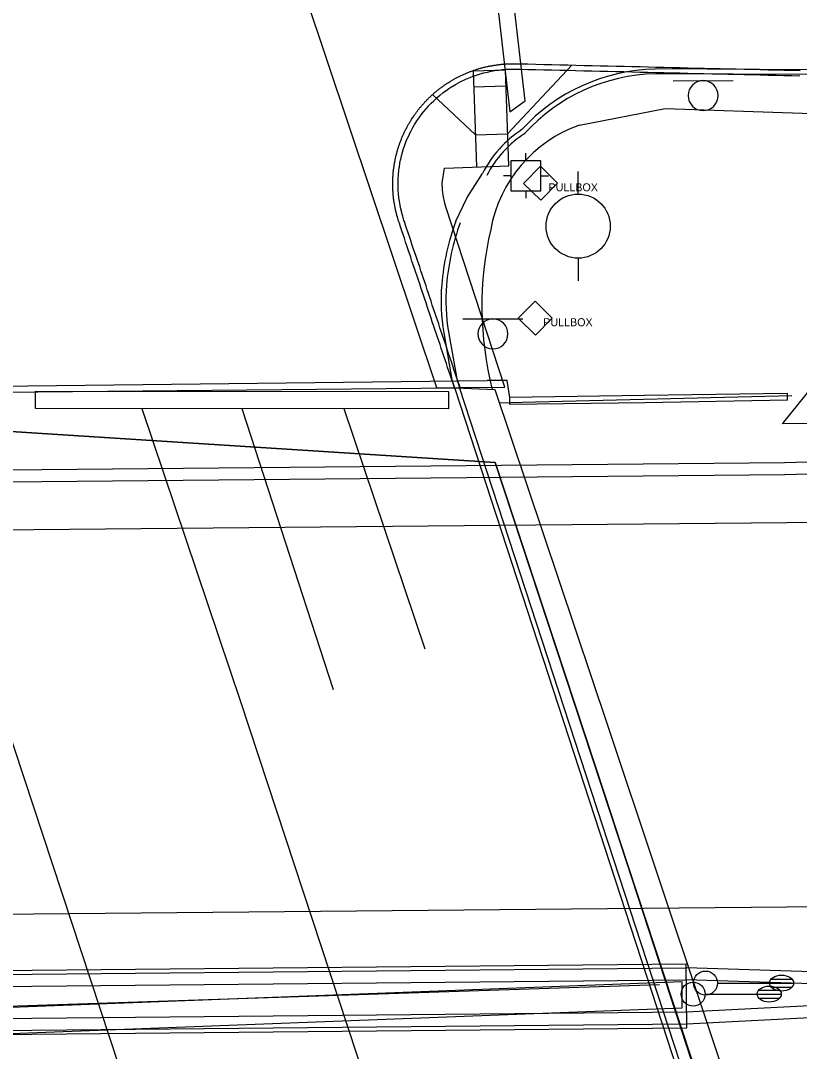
# Model space of a CAD drawing. Extents: x 2145380 to 2157287, y 139568 to 149130.
# Drawn here: x 2147326.9 to 2147424.2, y 143054.1 to 143182.8 of the extents above; entities that cross this region are included whole.
import ezdxf

# ---------------------------------------------------------------- set-up
doc = ezdxf.new("R2010")
doc.units = 0
for name, color, linetype in [('Default', 7, 'Continuous'), ('PR_PREVIOUSLY CONSTRUCTED', 7, 'Continuous'), ('TOPO_Asphalt', 7, 'Continuous'), ('TOPO_Bridge', 7, 'Continuous'), ('TOPO_BRIDGE_Floor Deck', 7, 'Continuous'), ('TOPO_BRIDGE_Low Beam', 7, 'Continuous'), ('TOPO_BRIDGE_Pier', 7, 'Continuous'), ('TOPO_BRIDGE_Pier Cap', 7, 'Continuous'), ('TOPO_Curb Back', 7, 'Continuous'), ('TOPO_Guardrail', 7, 'Continuous'), ('TOPO_Light Pole', 7, 'Continuous'), ('TOPO_Misc Line', 7, 'Continuous'), ('TOPO_Power Pole', 7, 'Continuous'), ('TOPO_Power Pullbox', 7, 'Continuous'), ('TOPO_Sign', 7, 'Continuous'), ('TOPO_Traffic Signal', 7, 'Continuous'), ('TOPO_Wall Freestanding', 7, 'Continuous')]:
    doc.layers.add(name, color=color, linetype=linetype)

# ---------------------------------------------------------------- blocks, each defined once
blk = doc.blocks.new('TRFSIG')
at = {"layer": 'TOPO_Traffic Signal'}
for p, q in [((0.04, 4.66), (0.04, 7.04)), ((-4.7, -0.09), (-7.08, -0.09)), ((4.79, -0.09), (7.17, -0.09)), ((0.04, -4.83), (0.04, -7.22))]:
    blk.add_line(p, q, dxfattribs=at)
blk.add_lwpolyline([(-4.7, -4.85), (4.81, -4.83), (4.79, 4.67), (-4.72, 4.66), (-4.7, -4.85)], dxfattribs=at)
blk = doc.blocks.new('LP')
at = {"layer": 'TOPO_Light Pole'}
blk.add_line((3.81, 0), (20.32, 0), dxfattribs=at)
for points in [[(20.32, 0), (27.94, 0)], [(20.32, 0), (23.5, 0)], [(20.83, 1.27), (27.43, 1.27)], [(20.83, 1.27), (23.5, 1.27)], [(23.71, 1.27), (27.43, 1.27)], [(23.71, 0), (27.94, 0)], [(20.83, -1.27), (27.43, -1.27)], [(20.83, -1.27), (23.5, -1.27)], [(23.71, -1.27), (27.43, -1.27)]]:
    blk.add_lwpolyline(points, dxfattribs=at)
blk.add_circle((0, 0), 3.81, dxfattribs=at)
blk.add_ellipse((24.13, 0), major_axis=(3.81, 0), ratio=0.666667, dxfattribs=at)
blk = doc.blocks.new('pulbox')
at = {"layer": 'Default'}
blk.add_lwpolyline([(-5.38, -0.01), (-0.02, 5.42), (5.4, 0.06), (0.05, -5.36), (-5.38, -0.01)], dxfattribs=at)
blk.add_text('PULLBOX', height=2.54, dxfattribs=at).set_placement((2.54, -2.54))
blk = doc.blocks.new('POWPOL')
at = {"layer": 'TOPO_Power Pole'}
for p, q in [((0, 10.16), (0, 17.34)), ((0, -10.16), (0, -17.34))]:
    blk.add_line(p, q, dxfattribs=at)
blk.add_circle((0, 0), 10.16, dxfattribs=at)

msp = doc.modelspace()

# ---------------------------------------------------------------- linework, layer by layer
at = {"layer": 'PR_PREVIOUSLY CONSTRUCTED'}
for p, q in [((2147383.47, 143176.5), (2147387.46, 143176.64)), ((2147383.88, 143164.51), (2147383.47, 143176.5)), ((2147387.88, 143164.65), (2147387.46, 143176.64)), ((2147387.74, 143168.65), (2147395.76, 143177.24)), ((2147383.54, 143174.51), (2147387.53, 143174.64)), ((2147378.35, 143173.54), (2147383.74, 143168.51)), ((2147383.74, 143168.51), (2147387.74, 143168.65)), ((2147379.84, 143164.37), (2147387.88, 143164.65)), ((2146746.76, 143113.71), (2147732.05, 143123.05)), ((2146353.97, 143061.98), (2147732.51, 143075.05)), ((2147293.38, 143063.89), (2147410.04, 143064.99)), ((2147293.38, 143063.39), (2147410.04, 143064.49)), ((2147410.12, 143056.99), (2147410.04, 143064.99)), ((2147468.57, 143062.61), (2147410.04, 143064.49)), ((2147293.4, 143061.89), (2147410.06, 143062.99)), ((2147457.08, 143061.48), (2147410, 143062.99)), ((2147410.03, 143058.99), (2147457.08, 143061.4)), ((2147410.11, 143057.49), (2147468.59, 143060.48)), ((2147293.44, 143057.89), (2147410.1, 143058.99)), ((2147293.45, 143056.39), (2147410.11, 143057.49)), ((2147293.45, 143055.89), (2147410.12, 143056.99))]:
    msp.add_line(p, q, dxfattribs=at)
for points in [[(2147378.9, 143136.92), (2147346.01, 143235.15), (2147354.74, 143238.07)], [(2147374.17, 143157.64), (2147374.12, 143157.78), (2147374.09, 143157.88), (2147374.06, 143157.98), (2147374.03, 143158.07), (2147374, 143158.17), (2147373.98, 143158.26), (2147373.95, 143158.36), (2147373.92, 143158.46), (2147373.9, 143158.55), (2147373.87, 143158.65), (2147373.85, 143158.75), (2147373.82, 143158.84), (2147373.8, 143158.94), (2147373.78, 143159.04), (2147373.75, 143159.14), (2147373.73, 143159.23), (2147373.71, 143159.33), (2147373.69, 143159.43), (2147373.67, 143159.53), (2147373.65, 143159.63), (2147373.64, 143159.72), (2147373.62, 143159.82), (2147373.6, 143159.92), (2147373.58, 143160.02), (2147373.57, 143160.12), (2147373.55, 143160.22), (2147373.54, 143160.32), (2147373.53, 143160.41), (2147373.51, 143160.51), (2147373.5, 143160.61), (2147373.49, 143160.71), (2147373.48, 143160.81), (2147373.47, 143160.91), (2147373.46, 143161.01), (2147373.45, 143161.11), (2147373.44, 143161.21), (2147373.43, 143161.31), (2147373.43, 143161.41), (2147373.42, 143161.51), (2147373.42, 143161.61), (2147373.41, 143161.71), (2147373.41, 143161.81), (2147373.4, 143161.91), (2147373.4, 143162.01), (2147373.4, 143162.11), (2147373.4, 143162.21), (2147373.4, 143162.31), (2147373.39, 143162.41), (2147373.4, 143162.51), (2147373.4, 143162.61), (2147373.4, 143162.71), (2147373.4, 143162.81), (2147373.4, 143162.91), (2147373.41, 143163.01), (2147373.41, 143163.11), (2147373.42, 143163.21), (2147373.42, 143163.31), (2147373.43, 143163.41), (2147373.44, 143163.51), (2147373.44, 143163.61), (2147373.45, 143163.71), (2147373.46, 143163.81), (2147373.47, 143163.91), (2147373.48, 143164.01), (2147373.49, 143164.11), (2147373.5, 143164.2), (2147373.52, 143164.3), (2147373.53, 143164.4), (2147373.54, 143164.5), (2147373.56, 143164.6), (2147373.57, 143164.7), (2147373.59, 143164.8), (2147373.6, 143164.9), (2147373.62, 143165), (2147373.64, 143165.09), (2147373.66, 143165.19), (2147373.68, 143165.29), (2147373.7, 143165.39), (2147373.72, 143165.49), (2147373.74, 143165.58), (2147373.76, 143165.68), (2147373.78, 143165.78), (2147373.8, 143165.88), (2147373.83, 143165.97), (2147373.85, 143166.07), (2147373.88, 143166.17), (2147373.9, 143166.26), (2147373.93, 143166.36), (2147373.96, 143166.46), (2147373.98, 143166.55), (2147374.01, 143166.65), (2147374.04, 143166.75), (2147374.07, 143166.84), (2147374.1, 143166.94), (2147374.13, 143167.03), (2147374.16, 143167.13), (2147374.19, 143167.22), (2147374.22, 143167.32), (2147374.26, 143167.41), (2147374.29, 143167.5), (2147374.33, 143167.6), (2147374.36, 143167.69), (2147374.4, 143167.79), (2147374.43, 143167.88), (2147374.47, 143167.97), (2147374.51, 143168.06), (2147374.54, 143168.16), (2147374.58, 143168.25), (2147374.62, 143168.34), (2147374.66, 143168.43), (2147374.7, 143168.52), (2147374.74, 143168.62), (2147374.79, 143168.71), (2147374.83, 143168.8), (2147374.87, 143168.89), (2147374.92, 143168.98), (2147374.96, 143169.07), (2147375, 143169.16), (2147375.05, 143169.25), (2147375.1, 143169.33), (2147375.14, 143169.42), (2147375.19, 143169.51), (2147375.24, 143169.6), (2147375.29, 143169.69), (2147375.33, 143169.77), (2147375.38, 143169.86), (2147375.43, 143169.95), (2147375.48, 143170.03), (2147375.54, 143170.12), (2147375.59, 143170.2), (2147375.64, 143170.29), (2147375.69, 143170.37), (2147375.75, 143170.46), (2147375.8, 143170.54), (2147375.85, 143170.63), (2147375.91, 143170.71), (2147375.97, 143170.79), (2147376.02, 143170.88), (2147376.08, 143170.96), (2147376.14, 143171.04), (2147376.19, 143171.12), (2147376.25, 143171.2), (2147376.31, 143171.28), (2147376.37, 143171.36), (2147376.43, 143171.44), (2147376.49, 143171.52), (2147376.55, 143171.6), (2147376.61, 143171.68), (2147376.68, 143171.76), (2147376.74, 143171.84), (2147376.8, 143171.92), (2147376.87, 143171.99), (2147376.93, 143172.07), (2147376.99, 143172.15), (2147377.06, 143172.22), (2147377.13, 143172.3), (2147377.19, 143172.37), (2147377.26, 143172.45), (2147377.33, 143172.52), (2147377.39, 143172.59), (2147377.46, 143172.67), (2147377.53, 143172.74), (2147377.6, 143172.81), (2147377.67, 143172.88), (2147377.74, 143172.95), (2147377.81, 143173.03), (2147377.88, 143173.1), (2147377.95, 143173.17), (2147378.02, 143173.24), (2147378.1, 143173.3), (2147378.17, 143173.37), (2147378.24, 143173.44), (2147378.32, 143173.51), (2147378.39, 143173.57), (2147378.47, 143173.64), (2147378.54, 143173.71), (2147378.62, 143173.77), (2147378.69, 143173.84), (2147378.77, 143173.9), (2147378.85, 143173.97), (2147378.92, 143174.03), (2147379, 143174.09), (2147379.08, 143174.15), (2147379.16, 143174.22), (2147379.24, 143174.28), (2147379.32, 143174.34), (2147379.4, 143174.4), (2147379.48, 143174.46), (2147379.56, 143174.52), (2147379.64, 143174.58), (2147379.72, 143174.63), (2147379.8, 143174.69), (2147379.88, 143174.75), (2147379.97, 143174.81), (2147380.05, 143174.86), (2147380.13, 143174.92), (2147380.22, 143174.97), (2147380.3, 143175.03), (2147380.38, 143175.08), (2147380.47, 143175.13), (2147380.55, 143175.18), (2147380.64, 143175.24), (2147380.73, 143175.29), (2147380.81, 143175.34), (2147380.9, 143175.39), (2147380.99, 143175.44), (2147381.07, 143175.49), (2147381.16, 143175.54), (2147381.25, 143175.58), (2147381.34, 143175.63), (2147381.42, 143175.68), (2147381.51, 143175.73), (2147381.6, 143175.77), (2147381.69, 143175.82), (2147381.78, 143175.86), (2147381.87, 143175.9), (2147381.96, 143175.95), (2147382.05, 143175.99), (2147382.14, 143176.03), (2147382.23, 143176.07), (2147382.32, 143176.11), (2147382.42, 143176.15), (2147382.51, 143176.19), (2147382.6, 143176.23), (2147382.69, 143176.27), (2147382.78, 143176.31), (2147382.88, 143176.35), (2147382.97, 143176.38), (2147383.06, 143176.42), (2147383.16, 143176.45), (2147383.25, 143176.49), (2147383.35, 143176.52), (2147383.44, 143176.56), (2147383.53, 143176.59), (2147383.63, 143176.62), (2147383.72, 143176.65), (2147383.82, 143176.68), (2147383.91, 143176.71), (2147384.01, 143176.74), (2147384.11, 143176.77), (2147384.2, 143176.8), (2147384.3, 143176.83), (2147384.39, 143176.85), (2147384.49, 143176.88), (2147384.59, 143176.91), (2147384.68, 143176.93), (2147384.78, 143176.96), (2147384.88, 143176.98), (2147384.98, 143177), (2147385.07, 143177.02), (2147385.17, 143177.05), (2147385.27, 143177.07), (2147385.37, 143177.09), (2147385.46, 143177.11), (2147385.56, 143177.13), (2147385.66, 143177.15), (2147385.76, 143177.16), (2147385.86, 143177.18), (2147385.96, 143177.2), (2147386.05, 143177.21), (2147386.15, 143177.23), (2147386.25, 143177.24), (2147386.35, 143177.26), (2147386.45, 143177.27), (2147386.55, 143177.28), (2147386.65, 143177.3), (2147386.75, 143177.31), (2147386.85, 143177.32), (2147386.95, 143177.33), (2147387.05, 143177.34), (2147387.15, 143177.35), (2147387.25, 143177.35), (2147387.35, 143177.36), (2147387.45, 143177.37), (2147387.55, 143177.37), (2147387.65, 143177.38), (2147387.75, 143177.38), (2147387.85, 143177.39), (2147387.94, 143177.39), (2147388.04, 143177.39), (2147388.14, 143177.4), (2147388.24, 143177.4), (2147388.34, 143177.4), (2147388.44, 143177.4), (2147388.54, 143177.4)], [(2147374.8, 143157.84), (2147374.64, 143158.36), (2147374.53, 143158.76), (2147374.52, 143158.82), (2147374.4, 143159.28), (2147374.32, 143159.69), (2147374.31, 143159.75), (2147374.23, 143160.22), (2147374.17, 143160.64), (2147374.16, 143160.69), (2147374.11, 143161.17), (2147374.09, 143161.59), (2147374.08, 143161.64), (2147374.06, 143162.12), (2147374.06, 143162.54), (2147374.06, 143162.6), (2147374.08, 143163.08), (2147374.1, 143163.5), (2147374.11, 143163.55), (2147374.15, 143164.03), (2147374.21, 143164.45), (2147374.22, 143164.5), (2147374.3, 143164.97), (2147374.38, 143165.39), (2147374.39, 143165.44), (2147374.5, 143165.91), (2147374.61, 143166.32), (2147374.62, 143166.37), (2147374.76, 143166.83), (2147374.9, 143167.23), (2147374.92, 143167.28), (2147375.09, 143167.72), (2147375.25, 143168.11), (2147375.27, 143168.16), (2147375.47, 143168.6), (2147375.66, 143168.98), (2147375.69, 143169.03), (2147375.91, 143169.45), (2147376.13, 143169.81), (2147376.16, 143169.86), (2147376.41, 143170.26), (2147376.65, 143170.61), (2147376.68, 143170.66), (2147376.96, 143171.04), (2147377.22, 143171.38), (2147377.26, 143171.42), (2147377.56, 143171.78), (2147377.85, 143172.1), (2147377.88, 143172.14), (2147378.21, 143172.49), (2147378.52, 143172.78), (2147378.55, 143172.82), (2147378.91, 143173.14), (2147379.23, 143173.42), (2147379.27, 143173.45), (2147379.64, 143173.75), (2147379.98, 143174), (2147380.03, 143174.03), (2147380.42, 143174.31), (2147380.78, 143174.54), (2147380.82, 143174.57), (2147381.23, 143174.81), (2147381.6, 143175.02), (2147381.65, 143175.04), (2147382.07, 143175.26), (2147382.46, 143175.44), (2147382.51, 143175.46), (2147382.95, 143175.65), (2147383.34, 143175.81), (2147383.39, 143175.83), (2147383.84, 143175.99), (2147384.24, 143176.12), (2147384.3, 143176.13), (2147384.76, 143176.26), (2147385.17, 143176.36), (2147385.22, 143176.37), (2147385.69, 143176.47), (2147386.1, 143176.55), (2147386.16, 143176.55), (2147386.63, 143176.62), (2147387.05, 143176.67), (2147387.11, 143176.67), (2147387.58, 143176.71), (2147388.01, 143176.72), (2147388.06, 143176.73), (2147388.54, 143176.73)], [(2147388.54, 143177.4), (2147389.28, 143177.39), (2147390.28, 143177.37), (2147391.28, 143177.34), (2147392.28, 143177.32), (2147393.28, 143177.3), (2147394.28, 143177.27), (2147395.28, 143177.25), (2147396.28, 143177.22), (2147397.28, 143177.2), (2147398.28, 143177.18), (2147399.28, 143177.15), (2147400.28, 143177.13), (2147401.28, 143177.11), (2147402.28, 143177.08), (2147403.28, 143177.06), (2147404.28, 143177.04), (2147405.28, 143177.01), (2147406.27, 143176.99), (2147407.27, 143176.97), (2147408.27, 143176.94), (2147409.27, 143176.92), (2147410.27, 143176.89), (2147411.27, 143176.87), (2147412.27, 143176.85), (2147413.27, 143176.82), (2147414.27, 143176.8), (2147415.27, 143176.78), (2147416.27, 143176.75), (2147417.27, 143176.73), (2147418.27, 143176.71), (2147419.27, 143176.68), (2147420.27, 143176.66), (2147421.27, 143176.64), (2147422.27, 143176.61), (2147423.27, 143176.59), (2147424.27, 143176.57)], [(2147388.54, 143176.73), (2147389.26, 143176.72), (2147390.26, 143176.7), (2147391.26, 143176.67), (2147392.26, 143176.65), (2147393.26, 143176.63), (2147394.26, 143176.6), (2147395.26, 143176.58), (2147396.26, 143176.56), (2147397.26, 143176.53), (2147398.26, 143176.51), (2147399.26, 143176.49), (2147400.26, 143176.46), (2147401.26, 143176.44), (2147402.26, 143176.42), (2147403.26, 143176.39), (2147404.26, 143176.37), (2147405.26, 143176.35), (2147406.26, 143176.32), (2147407.26, 143176.3), (2147408.26, 143176.27), (2147409.26, 143176.25), (2147410.26, 143176.23), (2147411.26, 143176.2), (2147412.26, 143176.18), (2147413.26, 143176.16), (2147414.26, 143176.13), (2147415.26, 143176.11), (2147416.26, 143176.09), (2147417.26, 143176.06), (2147418.26, 143176.04), (2147419.26, 143176.02), (2147420.26, 143175.99), (2147421.26, 143175.97), (2147422.25, 143175.94), (2147423.25, 143175.92), (2147424.25, 143175.9)], [(2147381.8, 143136.95), (2147387.39, 143137), (2147380.03, 143159.53), (2147379.89, 143160), (2147379.68, 143161), (2147379.6, 143161.66), (2147379.58, 143162.52), (2147379.84, 143164.37)], [(2147381.1, 143136.94), (2147380.88, 143137.58), (2147380.73, 143138.06), (2147380.57, 143138.53), (2147380.41, 143139.01), (2147380.25, 143139.48), (2147380.09, 143139.95), (2147379.93, 143140.43), (2147379.77, 143140.9), (2147379.61, 143141.38), (2147379.46, 143141.85), (2147379.3, 143142.33), (2147379.14, 143142.8), (2147378.98, 143143.27), (2147378.82, 143143.75), (2147378.66, 143144.22), (2147378.5, 143144.7), (2147378.34, 143145.17), (2147378.19, 143145.64), (2147378.03, 143146.12), (2147377.87, 143146.59), (2147377.71, 143147.07), (2147377.55, 143147.54), (2147377.39, 143148.01), (2147377.23, 143148.49), (2147377.07, 143148.96), (2147376.92, 143149.44), (2147376.76, 143149.91), (2147376.6, 143150.39), (2147376.44, 143150.86), (2147376.28, 143151.33), (2147376.12, 143151.81), (2147375.96, 143152.28), (2147375.8, 143152.76), (2147375.65, 143153.23), (2147375.49, 143153.7), (2147375.33, 143154.18), (2147375.17, 143154.65), (2147375.01, 143155.13), (2147374.85, 143155.6), (2147374.69, 143156.08), (2147374.53, 143156.55), (2147374.38, 143157.02), (2147374.22, 143157.5), (2147374.17, 143157.64)], [(2147381.1, 143136.94), (2147381.8, 143136.95), (2147381.36, 143138.27), (2147381.2, 143138.74), (2147381.04, 143139.21), (2147380.88, 143139.69), (2147380.72, 143140.16), (2147380.56, 143140.64), (2147380.41, 143141.11), (2147380.25, 143141.59), (2147380.09, 143142.06), (2147379.93, 143142.53), (2147379.77, 143143.01), (2147379.61, 143143.48), (2147379.45, 143143.96), (2147379.29, 143144.43), (2147379.14, 143144.9), (2147378.98, 143145.38), (2147378.82, 143145.85), (2147378.66, 143146.33), (2147378.5, 143146.8), (2147378.34, 143147.27), (2147378.18, 143147.75), (2147378.02, 143148.22), (2147377.87, 143148.7), (2147377.71, 143149.17), (2147377.55, 143149.65), (2147377.39, 143150.12), (2147377.23, 143150.59), (2147377.07, 143151.07), (2147376.91, 143151.54), (2147376.76, 143152.02), (2147376.6, 143152.49), (2147376.44, 143152.96), (2147376.28, 143153.44), (2147376.12, 143153.91), (2147375.96, 143154.39), (2147375.8, 143154.86), (2147375.64, 143155.34), (2147375.49, 143155.81), (2147375.33, 143156.28), (2147375.17, 143156.76), (2147375.01, 143157.23), (2147374.85, 143157.71), (2147374.8, 143157.84)], [(2146746.61, 143129.21), (2147125.89, 143132.8), (2147166.18, 143125.18), (2147422.32, 143127.61), (2147722.25, 143136.46), (2147731.92, 143136.55)], [(2147378.9, 143136.92), (2147381.1, 143136.94)], [(2147378.9, 143136.92), (2147381.11, 143136.91), (2147382.14, 143136.93)], [(2146746.63, 143127.71), (2147125.75, 143131.3), (2147166.04, 143123.68), (2147422.35, 143126.11), (2147722.28, 143134.96), (2147731.94, 143135.05)]]:
    msp.add_lwpolyline(points, dxfattribs=at)
msp.add_lwpolyline([(2147427.12, 143138.67), (2147444.59, 143160.15), (2147456.38, 143160.08), (2147481.36, 143161.2), (2147557, 143161.96), (2147557.25, 143136.26), (2147436.99, 143132.71), (2147436.94, 143134.51), (2147429.45, 143134.28), (2147429.51, 143132.49), (2147422.05, 143132.42)], close=True, dxfattribs=at)
at = {"layer": 'TOPO_Asphalt'}
msp.add_lwpolyline([(2147381.27, 143157.76), (2147382.68, 143160.7), (2147384.6, 143163.71)], dxfattribs=at)
at = {"layer": 'TOPO_Bridge'}
for points in [[(2147266.84, 143136.47), (2147385.2, 143137.85)], [(2147388, 143134.85), (2147388.02, 143135.73), (2147387.69, 143137.83), (2147385.2, 143137.85)]]:
    msp.add_lwpolyline(points, dxfattribs=at)
at = {"layer": 'TOPO_BRIDGE_Floor Deck'}
msp.add_lwpolyline([(2147436.61, 142985.9), (2147430.94, 142985.14), (2147374.14, 142984.81), (2147321.86, 142984.22), (2147317.02, 142984.28), (2147266.83, 143135.41), (2147272.28, 143136.04), (2147329.08, 143136.44), (2147381.28, 143136.94), (2147386.15, 143136.73), (2147400.2, 143094.81)], close=True, dxfattribs=at)
at = {"layer": 'TOPO_BRIDGE_Low Beam'}
for points in [[(2147269.78, 143135.04), (2147269.78, 143135.04), (2147386.2, 143127.6), (2147386.2, 143127.6)], [(2147386.2, 143127.6), (2147269.78, 143135.04), (2147281.68, 143099.17), (2147304.21, 143030.31), (2147315.63, 142995.71), (2147432.69, 142986.37), (2147415.55, 143038.12), (2147399.9, 143086.04)], [(2147269.78, 143135.04), (2147386.2, 143127.6), (2147432.69, 142986.37), (2147315.63, 142995.71)], [(2147386.2, 143127.6), (2147386.2, 143127.6), (2147399.9, 143086.04), (2147415.55, 143038.12), (2147432.69, 142986.37), (2147432.69, 142986.37)]]:
    msp.add_lwpolyline(points, close=True, dxfattribs=at)
msp.add_lwpolyline([(2147432.69, 142986.37), (2147415.55, 143038.12), (2147399.9, 143086.04), (2147386.2, 143127.6)], dxfattribs=at)
at = {"layer": 'TOPO_BRIDGE_Pier'}
for p, q in [((2147406.71, 143062.35), (2147295.93, 143058.72)), ((2147409.53, 143062.73), (2147409.53, 143062.73)), ((2147409.54, 143059.5), (2147409.54, 143059.5))]:
    msp.add_line(p, q, dxfattribs=at)
msp.add_lwpolyline([(2147293.05, 143055.06), (2147409.54, 143059.5), (2147409.53, 143062.73), (2147293.03, 143058.29)], close=True, dxfattribs=at)
msp.add_lwpolyline([(2147293.05, 143055.06), (2147409.54, 143059.5), (2147409.53, 143062.73), (2147293.03, 143058.29)], close=True, dxfattribs=at)
at = {"layer": 'TOPO_BRIDGE_Pier Cap'}
msp.add_lwpolyline([(2147409.54, 143059.5), (2147409.53, 143062.73), (2147293.03, 143058.29)], dxfattribs=at)
at = {"layer": 'TOPO_Curb Back'}
for points in [[(2147471.91, 143175.39), (2147425.73, 143176.64), (2147406.14, 143176.75)], [(2147471.89, 143174.79), (2147425.72, 143176.04), (2147406.14, 143176.15)], [(2147379.78, 143143.81), (2147380.79, 143137.92), (2147381.1, 143136.94)], [(2147380.37, 143143.92), (2147381.38, 143138.06), (2147381.74, 143136.92)], [(2147381.13, 143136.84), (2147413.47, 143037.83), (2147430.98, 142985.09)], [(2147381.7, 143137.03), (2147414.04, 143038.02), (2147431.55, 142985.28)]]:
    msp.add_lwpolyline(points, dxfattribs=at)
for centre, radius, start, end in [((2147406.67, 143153.54), 23.21, 91.3079, 137.6626), ((2147406.67, 143153.54), 22.61, 91.3293, 137.8558), ((2147397.39, 143157.16), 14.36, 123.2384, 152.8804), ((2147397.39, 143157.16), 13.76, 122.9235, 152.8804), ((2147409.64, 143147.31), 30.23, 159.7944, 175.2503), ((2147409.64, 143147.31), 29.63, 159.7944, 175.2515), ((2147402.82, 143147.83), 23.39, 175.1344, 189.8947), ((2147402.82, 143147.83), 22.79, 175.1328, 189.8969)]:
    msp.add_arc(centre, radius, start, end, dxfattribs=at)
at = {"layer": 'TOPO_Guardrail'}
msp.add_lwpolyline([(2147396.72, 143169.74), (2147407.41, 143171.81), (2147424.51, 143171.24), (2147484.91, 143169.71), (2147550.4, 143168.46), (2147576.68, 143168.04)], dxfattribs=at)
for centre, radius, start, end in [((2147402.37, 143153.7), 17.01, 109.4018, 169.7908), ((2147426.98, 143147.12), 42.45, 166.9407, 194.1823)]:
    msp.add_arc(centre, radius, start, end, dxfattribs=at)
at = {"layer": 'TOPO_Misc Line'}
for p, q in [((2147354.55, 143134.34), (2147365.96, 143099.27)), ((2147367.27, 143134.33), (2147377.42, 143104.33))]:
    msp.add_line(p, q, dxfattribs=at)
for points in [[(2147389.93, 143172.79), (2147385.03, 143215.16), (2147383.04, 143214.93), (2147388.02, 143171.39)], [(2147380.37, 143134.32), (2147328.78, 143134.36), (2147328.78, 143136.53), (2147380.37, 143136.48)]]:
    msp.add_lwpolyline(points, close=True, dxfattribs=at)
for points in [[(2147360.77, 142986.89), (2147326.16, 143091.87), (2147312.04, 143135.08)], [(2147342.08, 143134.35), (2147354.39, 143097.74), (2147373.37, 143040.11), (2147391.38, 142985.67)]]:
    msp.add_lwpolyline(points, dxfattribs=at)
at = {"layer": 'TOPO_Sign'}
for points in [[(2147408.4, 143175.28), (2147415.89, 143175.29)], [(2147412.15, 143175.28), (2147412.15, 143175.28)], [(2147410.28, 143173.42), (2147410.28, 143173.42)], [(2147414.01, 143173.42), (2147414.01, 143173.42)], [(2147412.15, 143171.55), (2147412.15, 143171.55)], [(2147382.16, 143145.53), (2147389.66, 143145.53)], [(2147385.91, 143145.53), (2147385.91, 143145.53)], [(2147384.05, 143143.66), (2147384.05, 143143.66)], [(2147387.78, 143143.66), (2147387.78, 143143.66)], [(2147385.91, 143141.79), (2147385.91, 143141.79)]]:
    msp.add_lwpolyline(points, dxfattribs=at)
for centre, start, end in [((2147412.15, 143173.42), 90, 180), ((2147412.15, 143173.42), 360, 90), ((2147412.15, 143173.42), 180, 270), ((2147412.15, 143173.42), 270, 0), ((2147385.91, 143143.66), 90, 180), ((2147385.91, 143143.66), 360, 90), ((2147385.91, 143143.66), 180, 270), ((2147385.91, 143143.66), 270, 0)]:
    msp.add_arc(centre, 1.87, start, end, dxfattribs=at)
at = {"layer": 'TOPO_Wall Freestanding'}
for points in [[(2147386.72, 143135.04), (2147389.55, 143135.14), (2147423.22, 143135.99)], [(2147422.69, 143135.39), (2147404.9, 143135.07), (2147388, 143134.85)], [(2147422.69, 143135.39), (2147422.71, 143136.22), (2147404.85, 143135.98), (2147388.02, 143135.73)]]:
    msp.add_lwpolyline(points, dxfattribs=at)

# ---------------------------------------------------------------- block references
at = {"layer": 'TOPO_Light Pole', "xscale": 0.39370000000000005, "yscale": 0.3937000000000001}
for p in [(2147412.45, 143062.59), (2147410.91, 143061.21)]:
    msp.add_blockref('LP', p, dxfattribs=at)
at = {"layer": 'TOPO_Power Pole', "xscale": 0.39370000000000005, "yscale": 0.3937000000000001}
msp.add_blockref('POWPOL', (2147396.55, 143157.12), dxfattribs=at)
at = {"layer": 'TOPO_Power Pullbox', "xscale": 0.39370000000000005, "yscale": 0.3937000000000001}
for p in [(2147391.85, 143162.47), (2147391.19, 143145.62)]:
    msp.add_blockref('pulbox', p, dxfattribs=at)
at = {"layer": 'TOPO_Traffic Signal', "xscale": 0.39370000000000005, "yscale": 0.3937000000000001}
msp.add_blockref('TRFSIG', (2147390.01, 143163.45), dxfattribs=at)

doc.saveas('drawing.dxf')
